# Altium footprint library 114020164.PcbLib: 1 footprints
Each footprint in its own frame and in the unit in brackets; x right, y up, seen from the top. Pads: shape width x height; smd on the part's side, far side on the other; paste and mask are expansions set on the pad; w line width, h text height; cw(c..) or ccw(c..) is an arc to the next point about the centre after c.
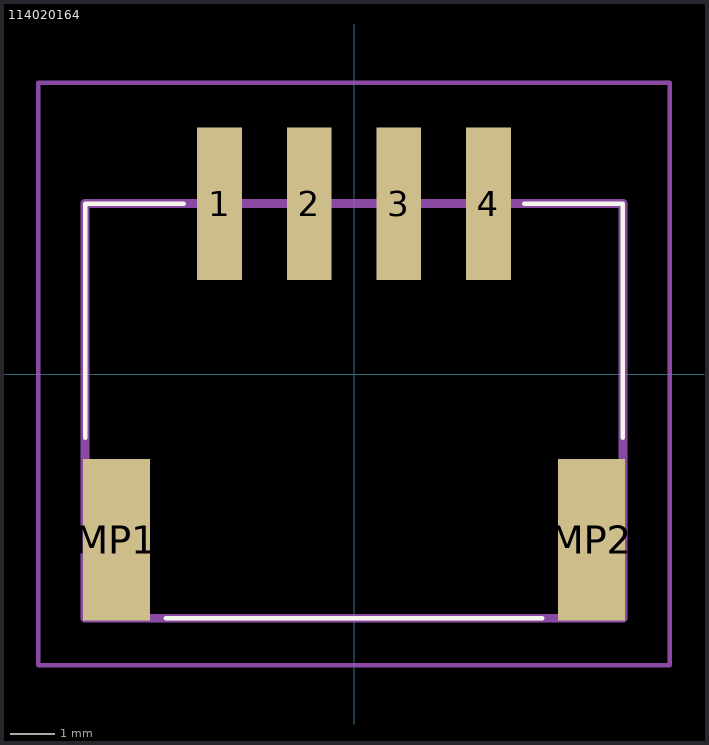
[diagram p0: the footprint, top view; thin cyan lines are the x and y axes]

## 114020164 [mm]
pads (6):
  rect 1x3.4 smd: 1(-3,3.8) 2(-1,3.8) 3(1,3.8) 4(3,3.8)
  rect 1.5x3.6 smd: MP1(-5.3,-3.7) MP2(5.3,-3.7)
Top Overlay:
  lines w0.1: -6,-1.425 -6,3.8 -3.8,3.8 ; -4.2,-5.45 4.2,-5.45 ; 3.8,3.8 6,3.8 6,-1.425
Mechanical 15:
  lines w0.2: -6,-5.45 6,-5.45 6,3.8 -6,3.8 -6,-5.45
Mechanical 20:
  lines w0.1: -7.05,-6.5 7.05,-6.5 7.05,6.5 -7.05,6.5 -7.05,-6.5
